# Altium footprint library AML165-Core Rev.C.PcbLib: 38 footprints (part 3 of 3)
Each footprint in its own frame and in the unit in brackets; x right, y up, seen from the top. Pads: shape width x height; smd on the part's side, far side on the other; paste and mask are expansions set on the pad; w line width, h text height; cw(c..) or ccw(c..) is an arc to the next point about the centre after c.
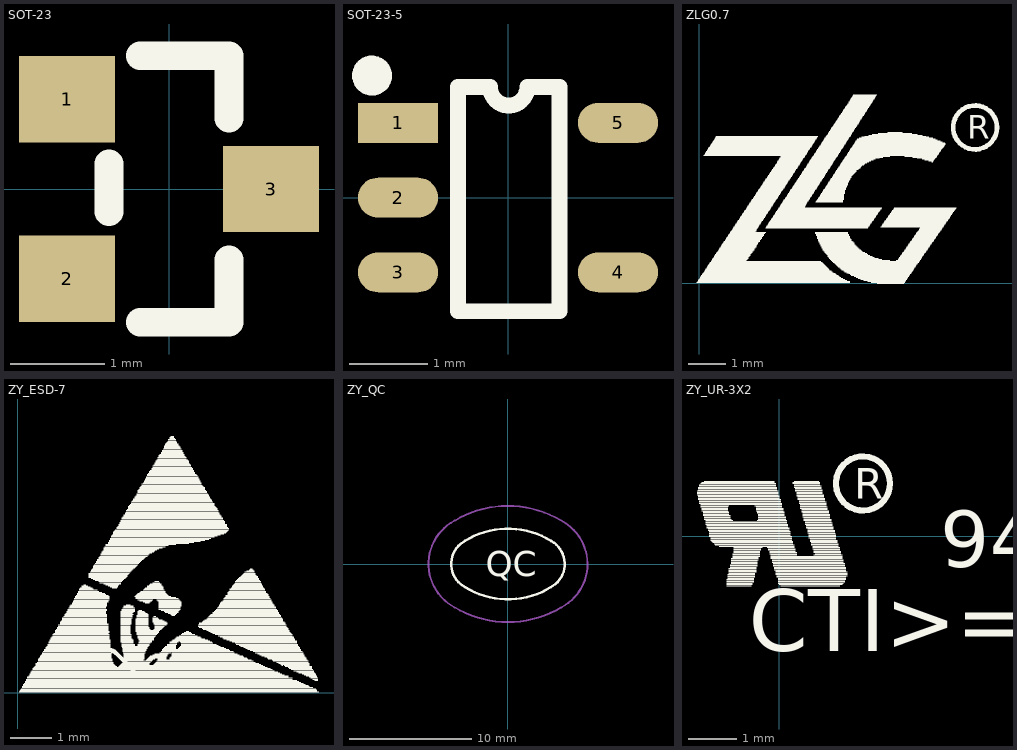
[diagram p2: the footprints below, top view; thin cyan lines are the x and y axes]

## SOT-23 [mil]
pads (3):
  rect 40x36 smd: 1(-42.5,37.4) 2(-42.5,-37.4) 3(42.5,0)
Top Overlay:
  lines w12: -25,-9.5 -25,10.5 ; -12,-55.5 25,-55.5 25,-29.5 ; -12,55.5 25,55.5 25,29.5
3D body: height 39.37, standoff -0.79, extent -47,-56.98 50.48,57.98

## SOT-23-5 [mil]
pads (5):
  rect 40x20 smd: 1(-55,37.4)
  oval 40x20 smd: 2(-55,0) 3(-55,-37.4) 4(55,-37.4) 5(55,37.4)
Top Overlay:
  circle w10: c-68,61 r5
  lines w7.87: -25,55.4 -25,-56.8 25.7,-56.8 25.7,55.4 ; -9,55.4 ccw(c0.35,55.4) 9.7,55.4
  lines w8: -25,55.4 -9,55.4 ; 9.7,55.4 25.7,55.4
3D body: height 42.79, standoff -0.51, extent -55.16,-57.06 55.09,57.09

## ZLG0.7 [mil] "7.8mmX5.6mm     不是太标准"
Top Overlay:
  drawing of 486 lines, arcs and shapes, not listed
  text "R" at 281,151 h25

## ZY_ESD-7 [mil]
height 7.87
Top Overlay:
  drawing of 546 lines, arcs and shapes, not listed

## ZY_QC [mil]
height 2
Top Overlay:
  lines w8: -152.68,64.82 ccw(c-98,0) -152.2,-65.23 ; -152.7,64.84 cw(c0.01,-148) 138.91,74.09 ; -152.19,-65.21 ccw(c-0.01,148) 152.7,-64.84 ; 139.77,73.81 cw(c98,0) 152.68,-64.82
  text "QC" at -71,-40.1 h81
Mechanical 15:
  lines w6: -172.01,139.49 ccw(c-98,0) -171.72,-139.64 ; -171.67,-139.56 ccw(c0.19,148) 171.82,-139.71 ; -171.62,139.71 cw(c0.01,-148) 169.76,140.81 ; 169.74,140.77 cw(c98.2,0) 172.21,-139.49

## ZY_UR-3X2 [mil]
height 7.87
Top Overlay:
  drawing of 193 lines, arcs and shapes, not listed
  text "94V-0" at 131,-25 h46
  text "R" at 61,30.5 h25
  text "CTI>=175" at -25,-110 h86.61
